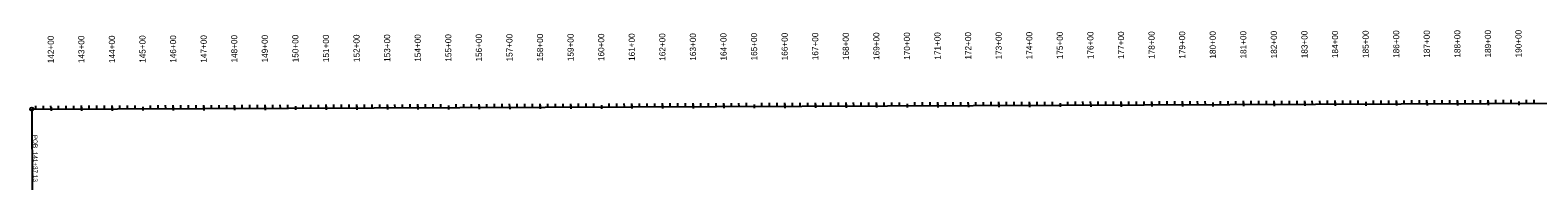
# Model space of a CAD drawing. Extents: x 22693007 to 22771804, y 6223023 to 6251673.
# Drawn here: x 22693007 to 22697937, y 6231240 to 6231762 of the extents above; entities that cross this region are included whole.
import ezdxf

# ---------------------------------------------------------------- set-up
doc = ezdxf.new("R2010")
doc.units = 0
for name, color, linetype in [('Default', 7, 'Continuous'), ('Draft_2', 7, 'Continuous'), ('NamedBoundary', 7, 'Continuous'), ('SheetBorder', 7, 'Continuous'), ('TextAlignment', 7, 'Continuous')]:
    doc.layers.add(name, color=color, linetype=linetype)

msp = doc.modelspace()

# ---------------------------------------------------------------- linework, layer by layer
at = {"layer": 'Default'}
msp.add_line((22693012, 6231503.8), (22700246.9, 6231532.6), dxfattribs=at)
at = {"layer": 'Draft_2'}
for p, q in [((22693074.9, 6231504), (22693074.8, 6231514.9)), ((22693174.9, 6231504.4), (22693174.8, 6231515.3)), ((22693274.9, 6231504.8), (22693274.8, 6231515.7)), ((22693374.9, 6231511.3), (22693374.9, 6231499.1)), ((22693474.9, 6231505.6), (22693474.8, 6231516.5)), ((22693574.9, 6231506), (22693574.8, 6231516.9)), ((22693674.9, 6231506.4), (22693674.8, 6231517.3)), ((22693774.9, 6231506.8), (22693774.8, 6231517.7)), ((22693874.9, 6231513.3), (22693874.9, 6231501.1)), ((22693974.9, 6231507.6), (22693974.8, 6231518.5)), ((22694074.9, 6231508), (22694074.8, 6231518.9)), ((22694174.9, 6231508.4), (22694174.8, 6231519.3)), ((22694274.9, 6231508.8), (22694274.8, 6231519.7)), ((22694374.8, 6231515.3), (22694374.9, 6231503.1)), ((22694474.9, 6231509.6), (22694474.8, 6231520.5)), ((22694574.9, 6231510), (22694574.8, 6231520.9)), ((22694674.9, 6231510.4), (22694674.8, 6231521.3)), ((22694774.9, 6231510.8), (22694774.8, 6231521.7)), ((22694874.8, 6231517.3), (22694874.9, 6231505.1)), ((22694974.9, 6231511.6), (22694974.8, 6231522.5)), ((22695074.9, 6231512), (22695074.8, 6231522.9)), ((22695174.9, 6231512.4), (22695174.8, 6231523.3)), ((22695274.9, 6231512.8), (22695274.8, 6231523.7)), ((22695374.8, 6231519.3), (22695374.9, 6231507.1)), ((22695474.9, 6231513.6), (22695474.8, 6231524.5)), ((22695574.9, 6231514), (22695574.8, 6231524.9)), ((22695674.9, 6231514.4), (22695674.8, 6231525.3)), ((22695774.9, 6231514.8), (22695774.8, 6231525.7)), ((22695874.8, 6231521.3), (22695874.9, 6231509.1)), ((22695974.9, 6231515.6), (22695974.8, 6231526.5)), ((22696074.9, 6231516), (22696074.8, 6231526.9)), ((22696174.9, 6231516.4), (22696174.8, 6231527.3)), ((22696274.9, 6231516.8), (22696274.8, 6231527.7)), ((22696374.8, 6231523.3), (22696374.9, 6231511.1)), ((22696474.9, 6231517.6), (22696474.8, 6231528.5)), ((22696574.9, 6231518), (22696574.8, 6231528.9)), ((22696674.9, 6231518.4), (22696674.8, 6231529.3)), ((22696774.9, 6231518.8), (22696774.8, 6231529.7)), ((22696874.8, 6231525.3), (22696874.9, 6231513)), ((22696974.9, 6231519.6), (22696974.8, 6231530.5)), ((22697074.9, 6231520), (22697074.8, 6231530.9)), ((22697174.9, 6231520.4), (22697174.8, 6231531.3)), ((22697274.9, 6231520.8), (22697274.8, 6231531.7)), ((22697374.8, 6231527.3), (22697374.9, 6231515)), ((22697474.8, 6231521.6), (22697474.8, 6231532.5)), ((22697574.8, 6231522), (22697574.8, 6231532.9)), ((22697674.8, 6231522.4), (22697674.8, 6231533.3)), ((22697774.8, 6231522.8), (22697774.8, 6231533.7)), ((22697874.8, 6231529.3), (22697874.9, 6231517))]:
    msp.add_line(p, q, dxfattribs=at)
at = {"layer": 'NamedBoundary'}
msp.add_line((22693012, 6231503.8), (22700246.9, 6231532.6), dxfattribs=at)
at = {"layer": 'SheetBorder'}
for p, q in [((22693024.9, 6231503.8), (22693024.8, 6231514.7)), ((22693049.9, 6231503.9), (22693049.8, 6231514.8)), ((22693074.9, 6231510.1), (22693074.9, 6231497.9)), ((22693099.9, 6231504.1), (22693099.8, 6231515)), ((22693124.9, 6231504.2), (22693124.8, 6231515.1)), ((22693149.9, 6231504.3), (22693149.8, 6231515.2)), ((22693174.9, 6231510.5), (22693174.9, 6231498.3)), ((22693199.9, 6231504.5), (22693199.8, 6231515.4)), ((22693224.9, 6231504.6), (22693224.8, 6231515.5)), ((22693249.9, 6231504.7), (22693249.8, 6231515.6)), ((22693274.9, 6231510.9), (22693274.9, 6231498.7)), ((22693299.9, 6231504.9), (22693299.8, 6231515.8)), ((22693324.9, 6231505), (22693324.8, 6231515.9)), ((22693349.9, 6231505.1), (22693349.8, 6231516)), ((22693374.9, 6231511.3), (22693374.9, 6231499.1)), ((22693399.9, 6231505.3), (22693399.8, 6231516.2)), ((22693424.9, 6231505.4), (22693424.8, 6231516.3)), ((22693449.9, 6231505.5), (22693449.8, 6231516.4)), ((22693474.9, 6231511.7), (22693474.9, 6231499.5)), ((22693499.9, 6231505.7), (22693499.8, 6231516.6)), ((22693524.9, 6231505.8), (22693524.8, 6231516.7)), ((22693549.9, 6231505.9), (22693549.8, 6231516.8)), ((22693574.9, 6231512.1), (22693574.9, 6231499.9)), ((22693599.9, 6231506.1), (22693599.8, 6231517)), ((22693624.9, 6231506.2), (22693624.8, 6231517.1)), ((22693649.9, 6231506.3), (22693649.8, 6231517.2)), ((22693674.9, 6231512.5), (22693674.9, 6231500.3)), ((22693699.9, 6231506.5), (22693699.8, 6231517.4)), ((22693724.9, 6231506.6), (22693724.8, 6231517.5)), ((22693749.9, 6231506.7), (22693749.8, 6231517.6)), ((22693774.9, 6231512.9), (22693774.9, 6231500.7)), ((22693799.9, 6231506.9), (22693799.8, 6231517.8)), ((22693824.9, 6231507), (22693824.8, 6231517.9)), ((22693849.9, 6231507.1), (22693849.8, 6231518)), ((22693874.9, 6231513.3), (22693874.9, 6231501.1)), ((22693899.9, 6231507.3), (22693899.8, 6231518.2)), ((22693924.9, 6231507.4), (22693924.8, 6231518.3)), ((22693949.9, 6231507.5), (22693949.8, 6231518.4)), ((22693974.9, 6231513.7), (22693974.9, 6231501.5)), ((22693999.9, 6231507.7), (22693999.8, 6231518.6)), ((22694024.9, 6231507.8), (22694024.8, 6231518.7)), ((22694049.9, 6231507.9), (22694049.8, 6231518.8)), ((22694074.9, 6231514.1), (22694074.9, 6231501.9)), ((22694099.9, 6231508.1), (22694099.8, 6231519)), ((22694124.9, 6231508.2), (22694124.8, 6231519.1)), ((22694149.9, 6231508.3), (22694149.8, 6231519.2)), ((22694174.9, 6231514.5), (22694174.9, 6231502.3)), ((22694199.9, 6231508.5), (22694199.8, 6231519.4)), ((22694224.9, 6231508.6), (22694224.8, 6231519.5)), ((22694249.9, 6231508.7), (22694249.8, 6231519.6)), ((22694274.8, 6231514.9), (22694274.9, 6231502.7)), ((22694299.9, 6231508.9), (22694299.8, 6231519.8)), ((22694324.9, 6231509), (22694324.8, 6231519.9)), ((22694349.9, 6231509.1), (22694349.8, 6231520)), ((22694374.8, 6231515.3), (22694374.9, 6231503.1)), ((22694399.9, 6231509.3), (22694399.8, 6231520.2)), ((22694424.9, 6231509.4), (22694424.8, 6231520.3)), ((22694449.9, 6231509.5), (22694449.8, 6231520.4)), ((22694474.8, 6231515.7), (22694474.9, 6231503.5)), ((22694499.9, 6231509.7), (22694499.8, 6231520.6)), ((22694524.9, 6231509.8), (22694524.8, 6231520.7)), ((22694549.9, 6231509.9), (22694549.8, 6231520.8)), ((22694574.8, 6231516.1), (22694574.9, 6231503.9)), ((22694599.9, 6231510.1), (22694599.8, 6231521)), ((22694624.9, 6231510.2), (22694624.8, 6231521.1)), ((22694649.9, 6231510.3), (22694649.8, 6231521.2)), ((22694674.8, 6231516.5), (22694674.9, 6231504.3)), ((22694699.9, 6231510.5), (22694699.8, 6231521.4)), ((22694724.9, 6231510.6), (22694724.8, 6231521.5)), ((22694749.9, 6231510.7), (22694749.8, 6231521.6)), ((22694774.8, 6231516.9), (22694774.9, 6231504.7)), ((22694799.9, 6231510.9), (22694799.8, 6231521.8)), ((22694824.9, 6231511), (22694824.8, 6231521.9)), ((22694849.9, 6231511.1), (22694849.8, 6231522)), ((22694874.8, 6231517.3), (22694874.9, 6231505.1)), ((22694899.9, 6231511.3), (22694899.8, 6231522.2)), ((22694924.9, 6231511.4), (22694924.8, 6231522.3)), ((22694949.9, 6231511.5), (22694949.8, 6231522.4)), ((22694974.8, 6231517.7), (22694974.9, 6231505.5)), ((22694999.9, 6231511.7), (22694999.8, 6231522.6)), ((22695024.9, 6231511.8), (22695024.8, 6231522.7)), ((22695049.9, 6231511.9), (22695049.8, 6231522.8)), ((22695074.8, 6231518.1), (22695074.9, 6231505.9)), ((22695099.9, 6231512.1), (22695099.8, 6231523)), ((22695124.9, 6231512.2), (22695124.8, 6231523.1)), ((22695149.9, 6231512.3), (22695149.8, 6231523.2)), ((22695174.8, 6231518.5), (22695174.9, 6231506.3)), ((22695199.9, 6231512.5), (22695199.8, 6231523.4)), ((22695224.9, 6231512.6), (22695224.8, 6231523.5)), ((22695249.9, 6231512.7), (22695249.8, 6231523.6)), ((22695274.8, 6231518.9), (22695274.9, 6231506.7)), ((22695299.9, 6231512.9), (22695299.8, 6231523.8)), ((22695324.9, 6231513), (22695324.8, 6231523.9)), ((22695349.9, 6231513.1), (22695349.8, 6231524)), ((22695374.8, 6231519.3), (22695374.9, 6231507.1)), ((22695399.9, 6231513.3), (22695399.8, 6231524.2)), ((22695424.9, 6231513.4), (22695424.8, 6231524.3)), ((22695449.9, 6231513.5), (22695449.8, 6231524.4)), ((22695474.8, 6231519.7), (22695474.9, 6231507.5)), ((22695499.9, 6231513.7), (22695499.8, 6231524.6)), ((22695524.9, 6231513.8), (22695524.8, 6231524.7)), ((22695549.9, 6231513.9), (22695549.8, 6231524.8)), ((22695574.8, 6231520.1), (22695574.9, 6231507.9)), ((22695599.9, 6231514.1), (22695599.8, 6231525)), ((22695624.9, 6231514.2), (22695624.8, 6231525.1)), ((22695649.9, 6231514.3), (22695649.8, 6231525.2)), ((22695674.8, 6231520.5), (22695674.9, 6231508.3)), ((22695699.9, 6231514.5), (22695699.8, 6231525.4)), ((22695724.9, 6231514.6), (22695724.8, 6231525.5)), ((22695749.9, 6231514.7), (22695749.8, 6231525.6)), ((22695774.8, 6231520.9), (22695774.9, 6231508.7)), ((22695799.9, 6231514.9), (22695799.8, 6231525.8)), ((22695824.9, 6231515), (22695824.8, 6231525.9)), ((22695849.9, 6231515.1), (22695849.8, 6231526)), ((22695874.8, 6231521.3), (22695874.9, 6231509.1)), ((22695899.9, 6231515.3), (22695899.8, 6231526.2)), ((22695924.9, 6231515.4), (22695924.8, 6231526.3)), ((22695949.9, 6231515.5), (22695949.8, 6231526.4)), ((22695974.8, 6231521.7), (22695974.9, 6231509.5)), ((22695999.9, 6231515.7), (22695999.8, 6231526.6)), ((22696024.9, 6231515.8), (22696024.8, 6231526.7)), ((22696049.9, 6231515.9), (22696049.8, 6231526.8)), ((22696074.8, 6231522.1), (22696074.9, 6231509.9)), ((22696099.9, 6231516.1), (22696099.8, 6231527)), ((22696124.9, 6231516.2), (22696124.8, 6231527.1)), ((22696149.9, 6231516.3), (22696149.8, 6231527.2)), ((22696174.8, 6231522.5), (22696174.9, 6231510.3)), ((22696199.9, 6231516.5), (22696199.8, 6231527.4)), ((22696224.9, 6231516.6), (22696224.8, 6231527.5)), ((22696249.9, 6231516.7), (22696249.8, 6231527.6)), ((22696274.8, 6231522.9), (22696274.9, 6231510.7)), ((22696299.9, 6231516.9), (22696299.8, 6231527.8)), ((22696324.9, 6231517), (22696324.8, 6231527.9)), ((22696349.9, 6231517.1), (22696349.8, 6231528)), ((22696374.8, 6231523.3), (22696374.9, 6231511.1)), ((22696399.9, 6231517.3), (22696399.8, 6231528.2)), ((22696424.9, 6231517.4), (22696424.8, 6231528.3)), ((22696449.9, 6231517.5), (22696449.8, 6231528.4)), ((22696474.8, 6231523.7), (22696474.9, 6231511.5)), ((22696499.9, 6231517.7), (22696499.8, 6231528.6)), ((22696524.9, 6231517.8), (22696524.8, 6231528.7)), ((22696549.9, 6231517.9), (22696549.8, 6231528.8)), ((22696574.8, 6231524.1), (22696574.9, 6231511.9)), ((22696599.9, 6231518.1), (22696599.8, 6231529)), ((22696624.9, 6231518.2), (22696624.8, 6231529.1)), ((22696649.9, 6231518.3), (22696649.8, 6231529.2)), ((22696674.8, 6231524.5), (22696674.9, 6231512.2)), ((22696699.9, 6231518.5), (22696699.8, 6231529.4)), ((22696724.9, 6231518.6), (22696724.8, 6231529.5)), ((22696749.9, 6231518.7), (22696749.8, 6231529.6)), ((22696774.8, 6231524.9), (22696774.9, 6231512.6)), ((22696799.9, 6231518.9), (22696799.8, 6231529.8)), ((22696824.9, 6231519), (22696824.8, 6231529.9)), ((22696849.9, 6231519.1), (22696849.8, 6231530)), ((22696874.8, 6231525.3), (22696874.9, 6231513)), ((22696899.9, 6231519.3), (22696899.8, 6231530.2)), ((22696924.9, 6231519.4), (22696924.8, 6231530.3)), ((22696949.9, 6231519.5), (22696949.8, 6231530.4)), ((22696974.8, 6231525.7), (22696974.9, 6231513.4)), ((22696999.9, 6231519.7), (22696999.8, 6231530.6)), ((22697024.9, 6231519.8), (22697024.8, 6231530.7)), ((22697049.9, 6231519.9), (22697049.8, 6231530.8)), ((22697074.8, 6231526.1), (22697074.9, 6231513.8)), ((22697099.9, 6231520.1), (22697099.8, 6231531)), ((22697124.9, 6231520.2), (22697124.8, 6231531.1)), ((22697149.9, 6231520.3), (22697149.8, 6231531.2)), ((22697174.8, 6231526.5), (22697174.9, 6231514.2)), ((22697199.9, 6231520.5), (22697199.8, 6231531.4)), ((22697224.9, 6231520.6), (22697224.8, 6231531.5)), ((22697249.9, 6231520.7), (22697249.8, 6231531.6)), ((22697274.8, 6231526.9), (22697274.9, 6231514.6)), ((22697299.8, 6231520.9), (22697299.8, 6231531.8)), ((22697324.8, 6231521), (22697324.8, 6231531.9)), ((22697349.8, 6231521.1), (22697349.8, 6231532)), ((22697374.8, 6231527.3), (22697374.9, 6231515)), ((22697399.8, 6231521.3), (22697399.8, 6231532.2)), ((22697424.8, 6231521.4), (22697424.8, 6231532.3)), ((22697449.8, 6231521.5), (22697449.8, 6231532.4)), ((22697474.8, 6231527.7), (22697474.9, 6231515.4)), ((22697499.8, 6231521.7), (22697499.8, 6231532.6)), ((22697524.8, 6231521.8), (22697524.8, 6231532.7)), ((22697549.8, 6231521.9), (22697549.8, 6231532.8)), ((22697574.8, 6231528.1), (22697574.9, 6231515.8)), ((22697599.8, 6231522.1), (22697599.8, 6231533)), ((22697624.8, 6231522.2), (22697624.8, 6231533.1)), ((22697649.8, 6231522.3), (22697649.8, 6231533.2)), ((22697674.8, 6231528.5), (22697674.9, 6231516.2)), ((22697699.8, 6231522.5), (22697699.8, 6231533.4)), ((22697724.8, 6231522.6), (22697724.8, 6231533.5)), ((22697749.8, 6231522.7), (22697749.8, 6231533.6)), ((22697774.8, 6231528.9), (22697774.9, 6231516.6)), ((22697799.8, 6231522.9), (22697799.8, 6231533.8)), ((22697824.8, 6231523), (22697824.8, 6231533.9)), ((22697849.8, 6231523.1), (22697849.8, 6231534)), ((22697874.8, 6231529.3), (22697874.9, 6231517)), ((22697899.8, 6231523.3), (22697899.8, 6231534.2)), ((22697924.8, 6231523.4), (22697924.8, 6231534.3))]:
    msp.add_line(p, q, dxfattribs=at)
at = {"layer": 'TextAlignment'}
for p in [(22693012, 6231503.8), (22693013.1, 6231239.8)]:
    msp.add_line(p, (22693013.1, 6231239.8), dxfattribs=at)
msp.add_circle((22693012, 6231503.8), 5.34, dxfattribs=at)

# ---------------------------------------------------------------- texts
at = {"layer": 'Draft_2'}
for s, p in [('160+00', (22694884.3, 6231661.2)), ('165+00', (22695384.3, 6231663.2)), ('170+00', (22695884.3, 6231665.2)), ('175+00', (22696384.3, 6231667.2)), ('180+00', (22696884.3, 6231669.2)), ('185+00', (22697384.3, 6231671.2)), ('190+00', (22697884.3, 6231673.2)), ('145+00', (22693384.3, 6231655.2)), ('150+00', (22693884.3, 6231657.2)), ('155+00', (22694384.3, 6231659.2))]:
    msp.add_text(s, height=20.04, rotation=90.2286, dxfattribs=at).set_placement(p)
at = {"layer": 'SheetBorder'}
for s, p in [('156+00', (22694484.3, 6231659.6)), ('157+00', (22694584.3, 6231660)), ('158+00', (22694684.3, 6231660.4)), ('159+00', (22694784.3, 6231660.8)), ('160+00', (22694884.3, 6231661.2)), ('161+00', (22694984.3, 6231661.6)), ('162+00', (22695084.3, 6231662)), ('163+00', (22695184.3, 6231662.4)), ('164+00', (22695284.3, 6231662.8)), ('165+00', (22695384.3, 6231663.2)), ('166+00', (22695484.3, 6231663.6)), ('167+00', (22695584.3, 6231664)), ('168+00', (22695684.3, 6231664.4)), ('169+00', (22695784.3, 6231664.8)), ('170+00', (22695884.3, 6231665.2)), ('171+00', (22695984.3, 6231665.6)), ('172+00', (22696084.3, 6231666)), ('173+00', (22696184.3, 6231666.4)), ('174+00', (22696284.3, 6231666.8)), ('175+00', (22696384.3, 6231667.2)), ('176+00', (22696484.3, 6231667.6)), ('177+00', (22696584.3, 6231668)), ('178+00', (22696684.3, 6231668.4)), ('179+00', (22696784.3, 6231668.8)), ('180+00', (22696884.3, 6231669.2)), ('181+00', (22696984.3, 6231669.6)), ('182+00', (22697084.3, 6231670)), ('183+00', (22697184.3, 6231670.4)), ('184+00', (22697284.3, 6231670.8)), ('185+00', (22697384.3, 6231671.2)), ('186+00', (22697484.3, 6231671.6)), ('187+00', (22697584.3, 6231672)), ('188+00', (22697684.3, 6231672.4)), ('189+00', (22697784.3, 6231672.8)), ('190+00', (22697884.3, 6231673.2)), ('142+00', (22693084.3, 6231654)), ('143+00', (22693184.3, 6231654.4)), ('144+00', (22693284.3, 6231654.8)), ('145+00', (22693384.3, 6231655.2)), ('146+00', (22693484.3, 6231655.6)), ('147+00', (22693584.3, 6231656)), ('148+00', (22693684.3, 6231656.4)), ('149+00', (22693784.3, 6231656.8)), ('150+00', (22693884.3, 6231657.2)), ('151+00', (22693984.3, 6231657.6)), ('152+00', (22694084.3, 6231658)), ('153+00', (22694184.3, 6231658.4)), ('154+00', (22694284.3, 6231658.8)), ('155+00', (22694384.3, 6231659.2))]:
    msp.add_text(s, height=20.04, rotation=90.2286, dxfattribs=at).set_placement(p)
at = {"layer": 'TextAlignment'}
for s, p in [('POB ', (22693015.6, 6231419.8)), ('141+37.13', (22693015.9, 6231364.3))]:
    msp.add_text(s, height=15, rotation=270.2286, dxfattribs=at).set_placement(p)

doc.saveas('drawing.dxf')
